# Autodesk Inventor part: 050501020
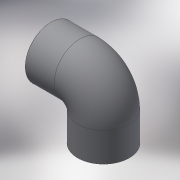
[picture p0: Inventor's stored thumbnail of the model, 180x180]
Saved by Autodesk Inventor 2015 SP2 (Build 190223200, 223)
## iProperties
Created: 2017-10
Part Number: 050501020
Material: Generic
Description: PLASSON THREADED 90° ELBOW PVC 2"
Document SubType Name: Modeling
Designer: KIM
Density: 1 g/cm^3
Appearance: Default
Author: KIM
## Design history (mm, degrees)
derived "050501.ipt"
feature "Solid1::050501.ipt"
tag "TaggingFeature1"
body "Solid1"
other parameters: "d7" = 0.56656, "d9" = 73, "d10" = 74.5, "d13" = 90 deg, "d19" = 90 deg, "d20" = 56.656, "d21" = 26, "d22" = 0, "d24" = 90 deg, "d26" = 50.9904, "d27" = 90 deg, "d28" = 26, "G_" = 56.656, "E_" = 73, "H_" = 111, "lt_" = 26
